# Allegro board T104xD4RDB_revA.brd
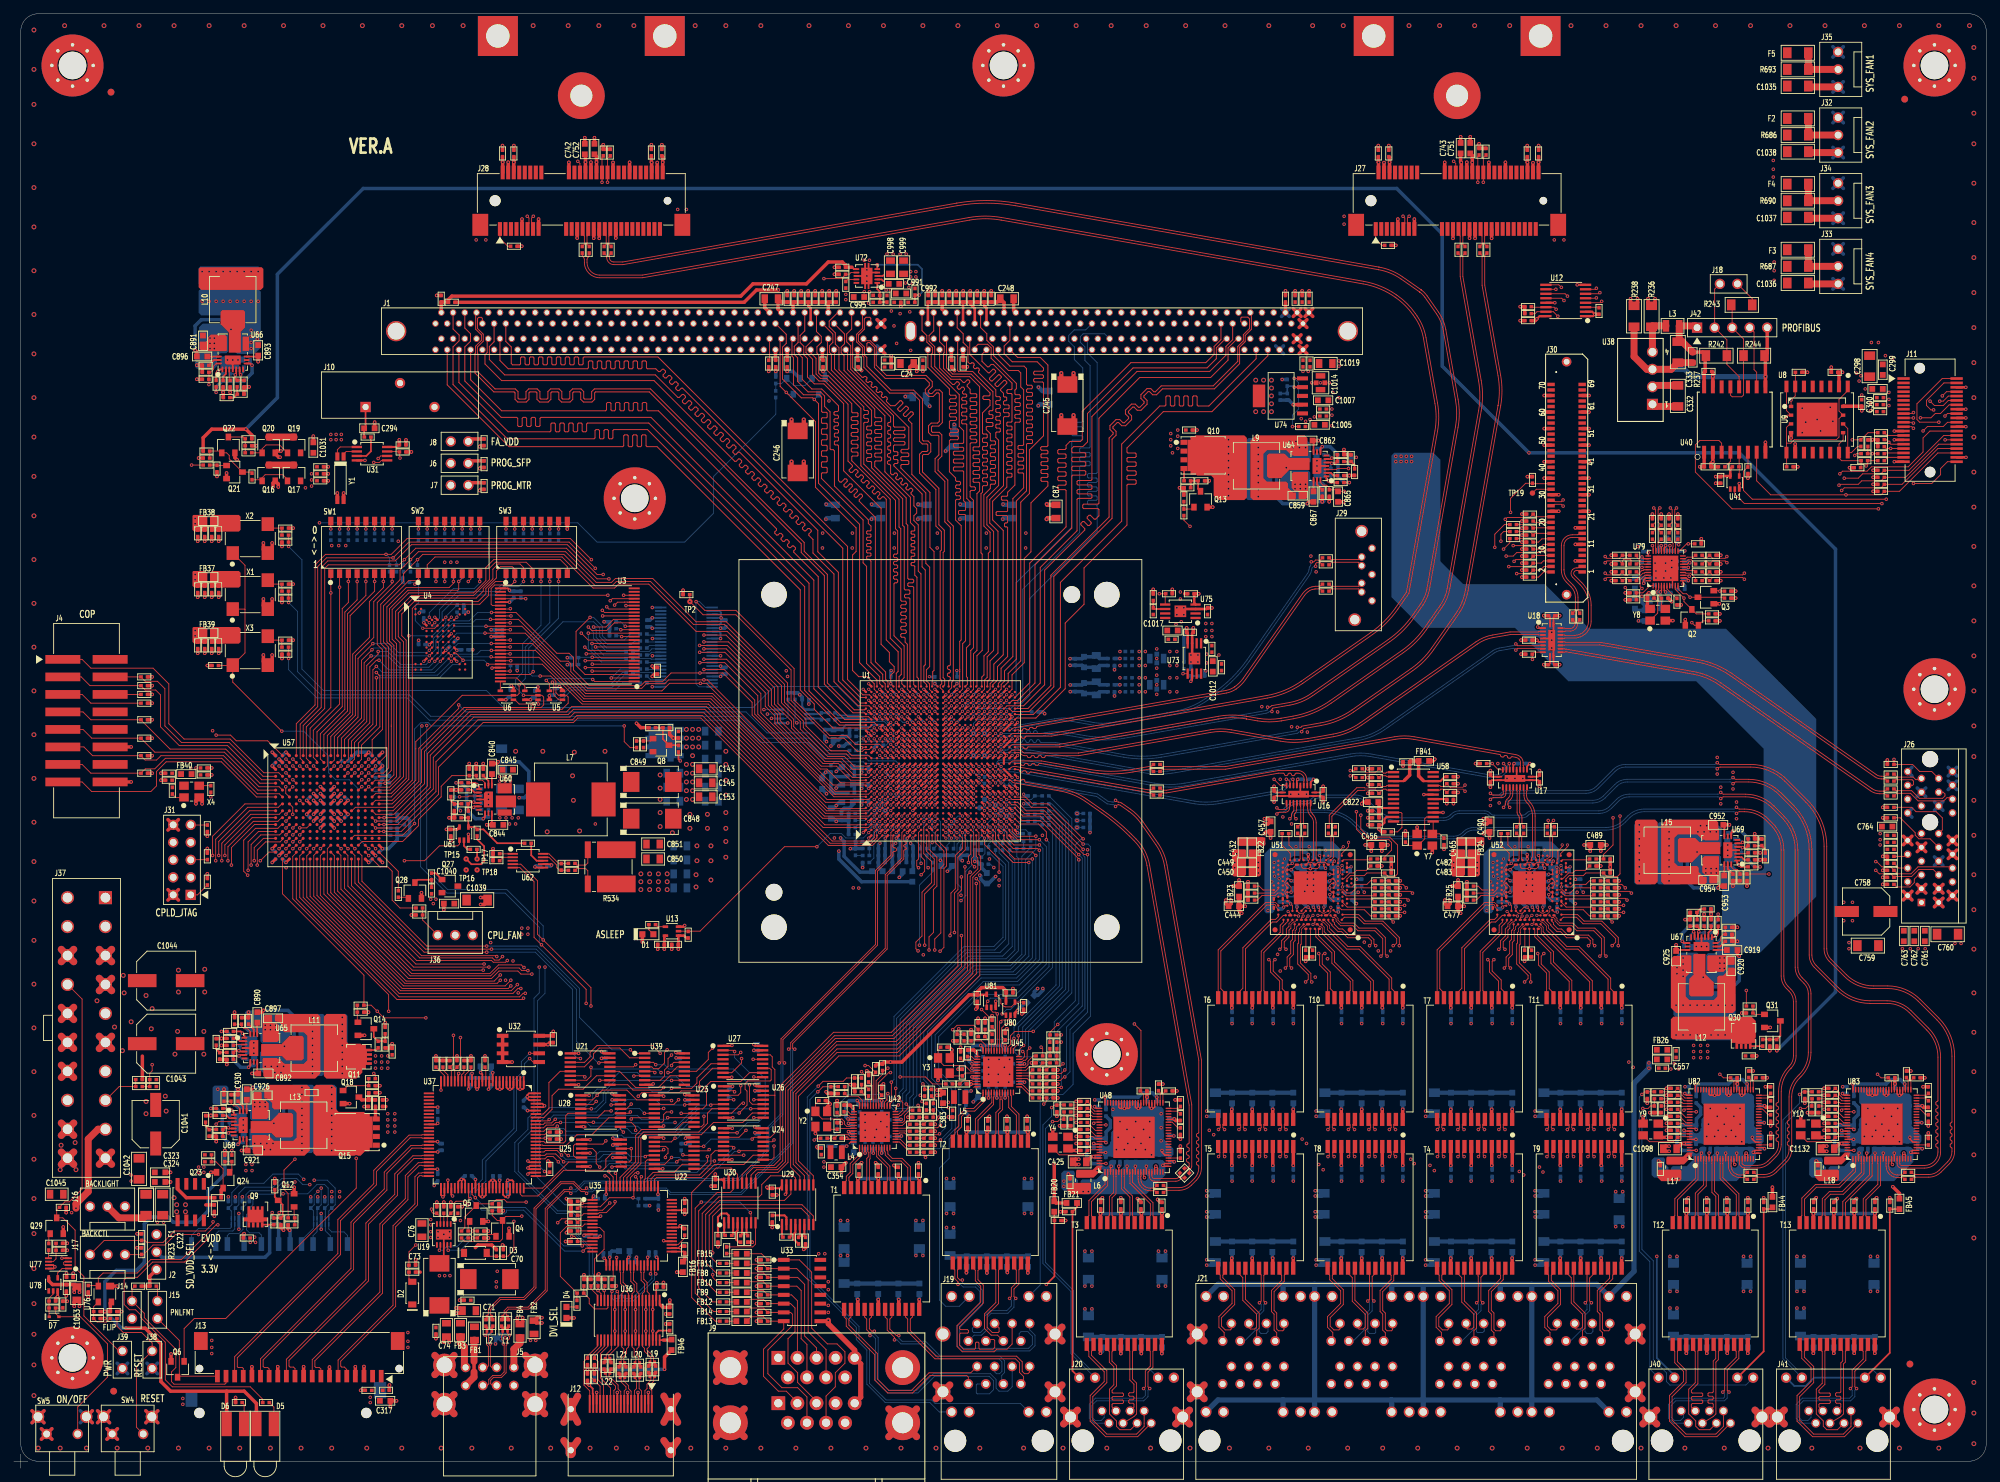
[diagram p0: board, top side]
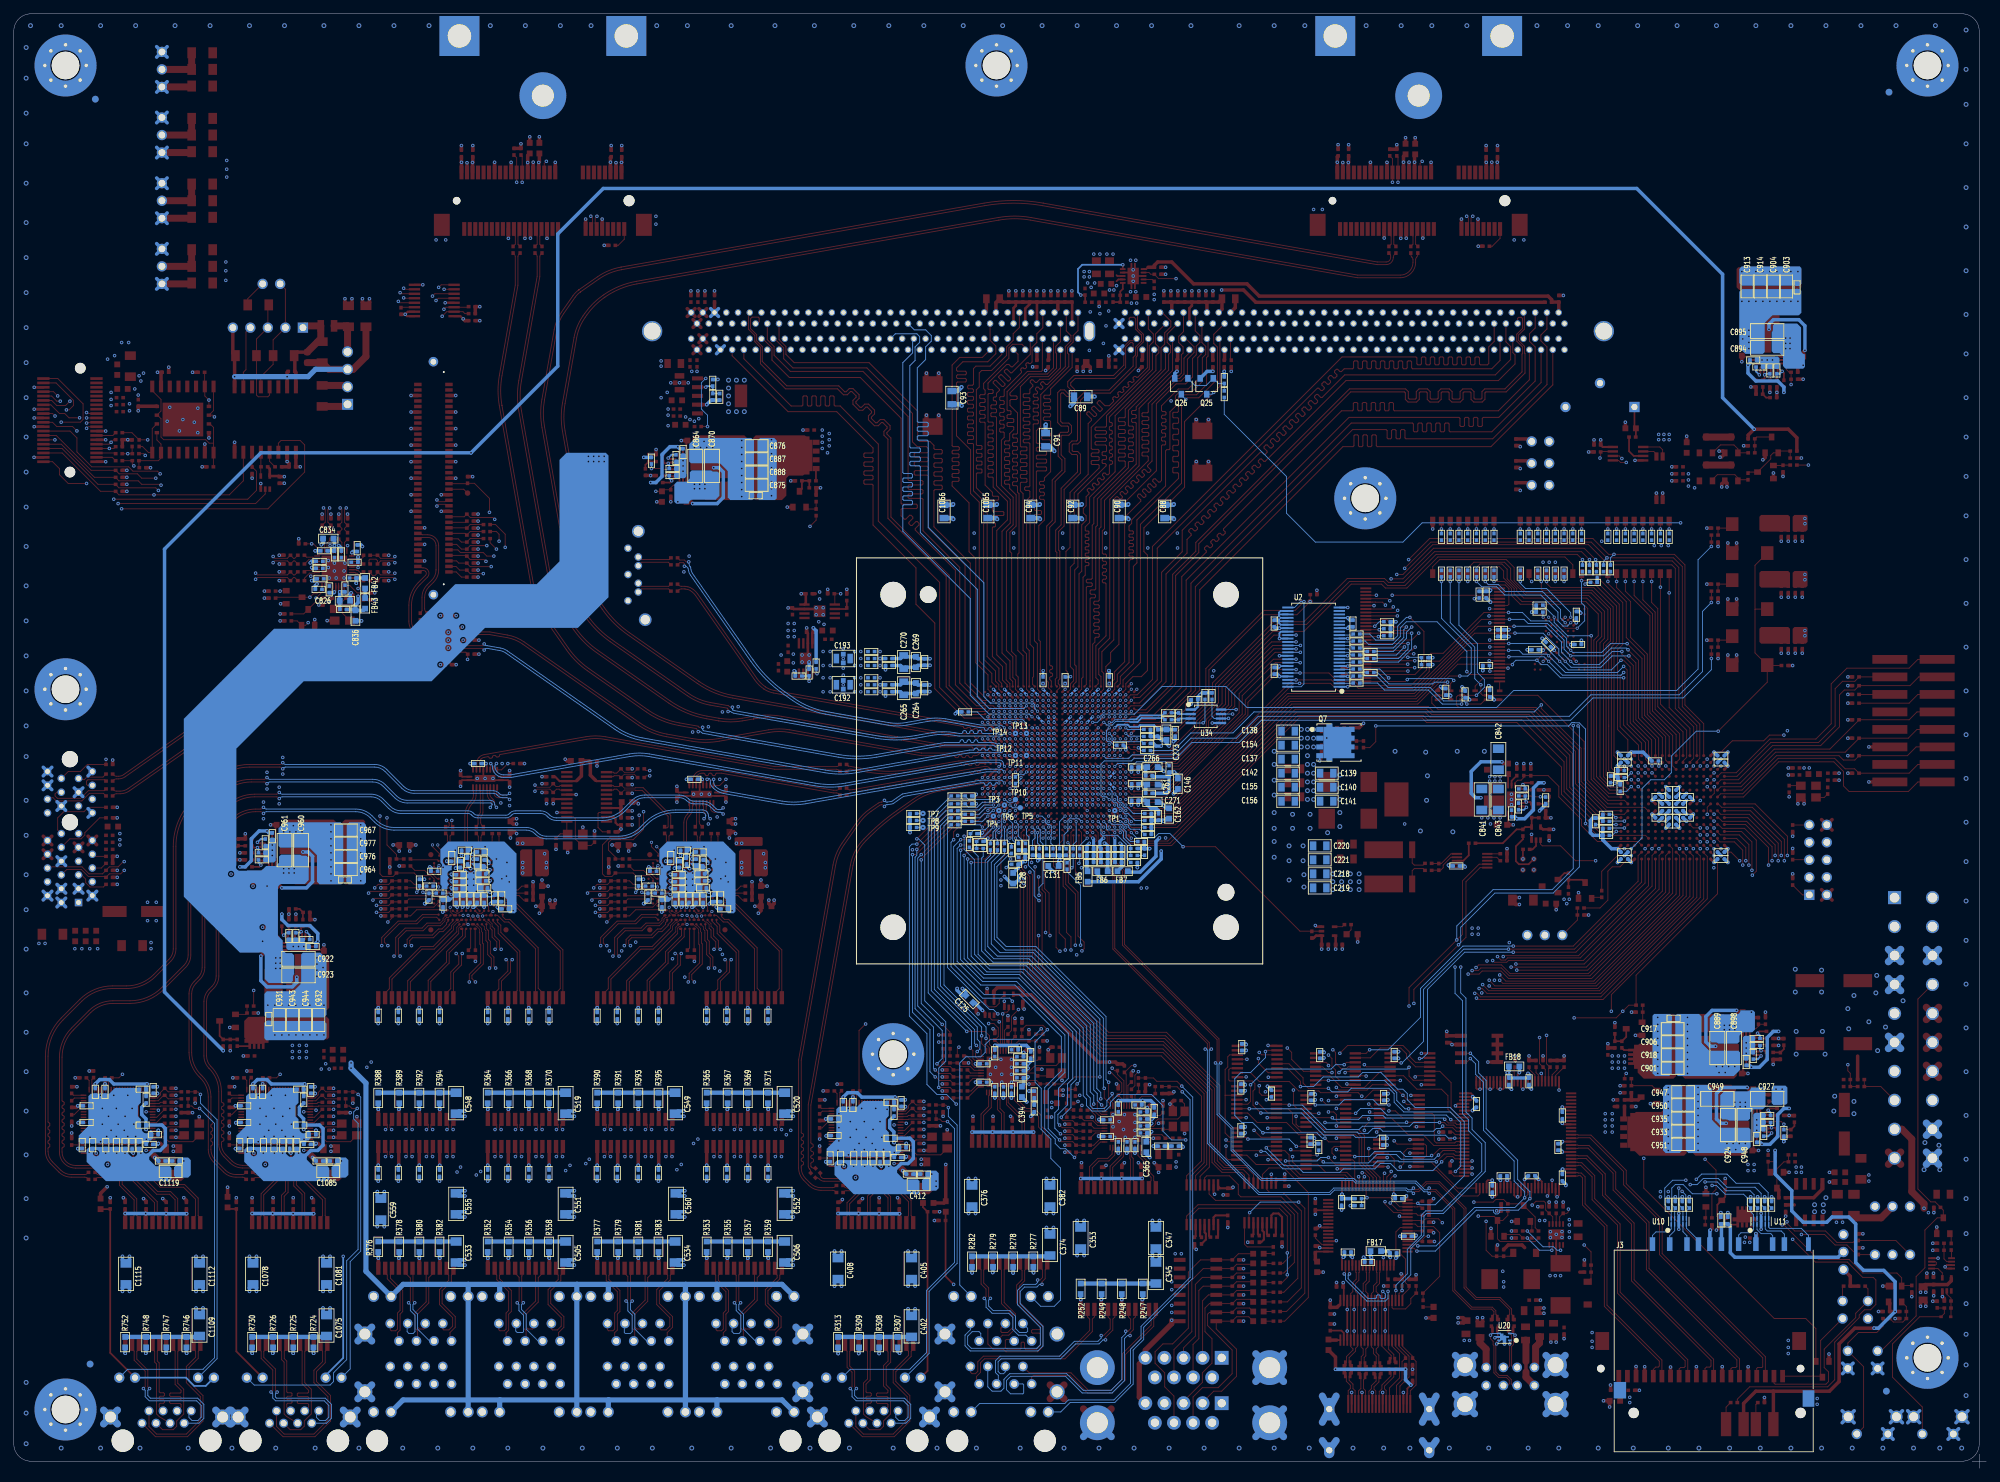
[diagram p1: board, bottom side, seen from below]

Outline 286.02 x 211.02 mm; copper layers: TOP, L2GND, L3SIG, L4PWR, L5PWR, L6SIG, L7GND, BOTTOM. Coordinates in mm from the lower left corner of the outline.
Outline path: 0,1.02 2.03,1.02 ; 1.02,2.03 1.02,0 ; 1.02,208.52 arc(1.75,210.28) 3.52,211.02 283.52,211.02 arc(285.28,210.28) 286.02,208.52 286.02,3.52 arc(285.28,1.75) 283.52,1.02 3.52,1.02 arc(1.75,1.75) 1.02,3.52 1.02,208.52

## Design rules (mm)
net group AURORA_EVTI_N: nets AURORA_EVTI_N N17558754
net group AURORA_EVTO_N: nets AURORA_EVTO_N N17558775
net group AURORA_HALT_N: nets AURORA_HALT_N N17558733
net group AURORA_REFCLK_N: nets AURORA_REFCLK_N N17952605
net group AURORA_REFCLK_P: nets AURORA_REFCLK_P N17952607
net group AURORA_RX_N: nets AURORA_RX_N N17557628
net group AURORA_RX_P: nets AURORA_RX_P N17557626
net group AURORA_TX: nets AURORA_TX_N AURORA_TX_P
net group CKE_ISO_EN: nets CKE_ISO_EN N20553507
net group CPLD_REFCLK: nets CPLD_REFCLK N17708927
net group DDR_REFCLK: nets DDR_REFCLK N17232338
net group EC1_INT_N: nets EC1_INT_N N17588858
net group EC1_LED0: nets EC1_LED0 N16870836
net group EC1_LED1: nets EC1_LED1 N16870842
net group EC1_MDI0: nets EC1_MDI0_N EC1_MDI0_P
net group EC1_MDI1: nets EC1_MDI1_N EC1_MDI1_P
net group EC1_MDI2: nets EC1_MDI2_N EC1_MDI2_P
net group EC1_MDI3: nets EC1_MDI3_N EC1_MDI3_P
net group EC1_MDX0: nets EC1_MDX0_N EC1_MDX0_P
net group EC1_MDX1: nets EC1_MDX1_N EC1_MDX1_P
net group EC1_MDX2: nets EC1_MDX2_N EC1_MDX2_P
net group EC1_MDX3: nets EC1_MDX3_N EC1_MDX3_P
net group EC1_PME_N: nets EC1_PME_N N17588905
net group EC1_REFCLK: nets EC1_REFCLK N17588897
net group EC2_INT_N: nets EC2_INT_N N17590707
net group EC2_LED0: nets EC2_LED0 N16974534
net group EC2_LED1: nets EC2_LED1 N16974536
net group EC2_MDI0: nets EC2_MDI0_N EC2_MDI0_P
net group EC2_MDI1: nets EC2_MDI1_N EC2_MDI1_P
net group EC2_MDI2: nets EC2_MDI2_N EC2_MDI2_P
net group EC2_MDI3: nets EC2_MDI3_N EC2_MDI3_P
net group EC2_MDX0: nets EC2_MDX0_N EC2_MDX0_P
net group EC2_MDX1: nets EC2_MDX1_N EC2_MDX1_P
net group EC2_MDX2: nets EC2_MDX2_N EC2_MDX2_P
net group EC2_MDX3: nets EC2_MDX3_N EC2_MDX3_P
net group EC2_PME_N: nets EC2_PME_N N17590774
net group EC2_REFCLK: nets EC2_REFCLK N17590767
net group EVDD_SEL: nets EVDD_SEL N20559490
net group FAN_PWM: nets FAN_PWM N17598342
net group FAN_TACH: nets FAN_TACH N17597092
net group GVDD_EN_N: nets GVDD_EN_N N19623885
net group IOPWR_EN: nets IOPWR_EN N18275588
net group LED_STATUS: nets LED_STATUS N22361656
net group MPEX1_REFCLK_N: nets MPEX1_REFCLK_N N17952565
net group MPEX1_REFCLK_P: nets MPEX1_REFCLK_P N17952563
net group MPEX1_RX_N: nets MPEX1_RX_N N16984265
net group MPEX1_RX_P: nets MPEX1_RX_P N16984263
net group MPEX1_TX_N: nets MPEX1_TX_N N16984233
net group MPEX1_TX_P: nets MPEX1_TX_P N16984231
net group MPEX2_REFCLK_N: nets MPEX2_REFCLK_N N17952569
net group MPEX2_REFCLK_P: nets MPEX2_REFCLK_P N17952567
net group MPEX2_RX_N: nets MPEX2_RX_N N16985388
net group MPEX2_RX_P: nets MPEX2_RX_P N16985386
net group MPEX2_TX_N: nets MPEX2_TX_N N16985356
net group MPEX2_TX_P: nets MPEX2_TX_P N16985354
net group N17055373: nets N17055373 N17055376
net group N17055394: nets N17055394 N17055396
net group N17055422: nets N17055422 N17055507
net group N17055459: nets N17055459 N17055529
net group N17055495: nets N17055419 N17055495
net group N17055527: nets N17055461 N17055527
net group N17056740: nets N17056740 N17056750
net group N17056764: nets N17056764 N17056766
net group N17056778: nets N17056778 N17056834
net group N17056796: nets N17056796 N17056846
net group N17056816: nets N17056776 N17056816
net group N17056844: nets N17056798 N17056844
net group N17246771: nets N17246719 N17246771
net group N17251677: nets N17251677 N17251680
net group N17251765: nets N17251765 N17251768
net group N17321019: nets N17321001 N17321019
net group N17399246: nets N17399246 N17399288
net group N17401544: nets N17400346 N17401544
net group N17424508: nets N17424508 N17424523
net group N17525004: nets N17525004 N17596169
net group N17639958: nets N17639958 N17639964
net group N17696038: nets N17696038 N17696060
net group N17742094: nets N17742094 N18275595
net group N18177051: nets N18177051 N18177080
net group N18275529: nets N18275529 N18275540
net group N18275559: nets N18275559 N18275570
net group N18569886: nets N17523697 N18569886
net group N19623883: nets N19623883 N19623968
net group N19675149: nets N19675149 N19675151
net group N20559492: nets N20559492 N20559589
net group N20559669: nets N20559669 N20559724
net group N23926306: nets N23926306 N23926329
net group PEX_REFCLK_N: nets N17952440 PEX_REFCLK_N
net group PEX_REFCLK_P: nets N17952438 PEX_REFCLK_P
net group PEX_RX_N: nets N17249127 PEX_RX_N
net group PEX_RX_P: nets N17249129 PEX_RX_P
net group PEX_TX_N: nets N17249250 PEX_TX_N
net group PEX_TX_P: nets N17249252 PEX_TX_P
net group PWR_GOOD: nets N18569887 PWR_GOOD
net group QSG1_INT_N: nets N17584869 QSG1_INT_N
net group QSG1_LED0: nets N17584990 QSG1_LED0
net group QSG1_LED1: nets N17584987 QSG1_LED1
net group QSG1_MDI0: nets QSG1_MDI0_N QSG1_MDI0_P
net group QSG1_MDI1: nets QSG1_MDI1_N QSG1_MDI1_P
net group QSG1_MDI2: nets QSG1_MDI2_N QSG1_MDI2_P
net group QSG1_MDI3: nets QSG1_MDI3_N QSG1_MDI3_P
net group QSG1_MDX0: nets QSG1_MDX0_N QSG1_MDX0_P
net group QSG1_MDX1: nets QSG1_MDX1_N QSG1_MDX1_P
net group QSG1_MDX2: nets QSG1_MDX2_N QSG1_MDX2_P
net group QSG1_MDX3: nets QSG1_MDX3_N QSG1_MDX3_P
net group QSG1_REFCLK_N: nets N17823659 QSG1_REFCLK_N
net group QSG1_REFCLK_P: nets N17823662 QSG1_REFCLK_P
net group QSG2_INT_N: nets N17640717 QSG2_INT_N
net group QSG2_LED0: nets N17585018 QSG2_LED0
net group QSG2_LED1: nets N17585015 QSG2_LED1
net group QSG2_MDI0: nets QSG2_MDI0_N QSG2_MDI0_P
net group QSG2_MDI1: nets QSG2_MDI1_N QSG2_MDI1_P
net group QSG2_MDI2: nets QSG2_MDI2_N QSG2_MDI2_P
net group QSG2_MDI3: nets QSG2_MDI3_N QSG2_MDI3_P
net group QSG2_MDX0: nets QSG2_MDX0_N QSG2_MDX0_P
net group QSG2_MDX1: nets QSG2_MDX1_N QSG2_MDX1_P
net group QSG2_MDX2: nets QSG2_MDX2_N QSG2_MDX2_P
net group QSG2_MDX3: nets QSG2_MDX3_N QSG2_MDX3_P
net group QSG2_REFCLK_N: nets N17824163 QSG2_REFCLK_N
net group QSG2_REFCLK_P: nets N17824166 QSG2_REFCLK_P
net group QSG3_LED0: nets N17585038 QSG3_LED0
net group QSG3_LED1: nets N17585035 QSG3_LED1
net group QSG3_MDI0: nets QSG3_MDI0_N QSG3_MDI0_P
net group QSG3_MDI1: nets QSG3_MDI1_N QSG3_MDI1_P
net group QSG3_MDI2: nets QSG3_MDI2_N QSG3_MDI2_P
net group QSG3_MDI3: nets QSG3_MDI3_N QSG3_MDI3_P
net group QSG3_MDX0: nets QSG3_MDX0_N QSG3_MDX0_P
net group QSG3_MDX1: nets QSG3_MDX1_N QSG3_MDX1_P
net group QSG3_MDX2: nets QSG3_MDX2_N QSG3_MDX2_P
net group QSG3_MDX3: nets QSG3_MDX3_N QSG3_MDX3_P
net group QSG4_LED0: nets N17585058 QSG4_LED0
net group QSG4_LED1: nets N17585055 QSG4_LED1
net group QSG4_MDI0: nets QSG4_MDI0_N QSG4_MDI0_P
net group QSG4_MDI1: nets QSG4_MDI1_N QSG4_MDI1_P
net group QSG4_MDI2: nets QSG4_MDI2_N QSG4_MDI2_P
net group QSG4_MDI3: nets QSG4_MDI3_N QSG4_MDI3_P
net group QSG4_MDX0: nets QSG4_MDX0_N QSG4_MDX0_P
net group QSG4_MDX1: nets QSG4_MDX1_N QSG4_MDX1_P
net group QSG4_MDX2: nets QSG4_MDX2_N QSG4_MDX2_P
net group QSG4_MDX3: nets QSG4_MDX3_N QSG4_MDX3_P
net group QSG5_LED0: nets N17585295 QSG5_LED0
net group QSG5_LED1: nets N17585292 QSG5_LED1
net group QSG5_MDI0: nets QSG5_MDI0_N QSG5_MDI0_P
net group QSG5_MDI1: nets QSG5_MDI1_N QSG5_MDI1_P
net group QSG5_MDI2: nets QSG5_MDI2_N QSG5_MDI2_P
net group QSG5_MDI3: nets QSG5_MDI3_N QSG5_MDI3_P
net group QSG5_MDX0: nets QSG5_MDX0_N QSG5_MDX0_P
net group QSG5_MDX1: nets QSG5_MDX1_N QSG5_MDX1_P
net group QSG5_MDX2: nets QSG5_MDX2_N QSG5_MDX2_P
net group QSG5_MDX3: nets QSG5_MDX3_N QSG5_MDX3_P
net group QSG6_LED0: nets N17585315 QSG6_LED0
net group QSG6_LED1: nets N17585312 QSG6_LED1
net group QSG6_MDI0: nets QSG6_MDI0_N QSG6_MDI0_P
net group QSG6_MDI1: nets QSG6_MDI1_N QSG6_MDI1_P
net group QSG6_MDI2: nets QSG6_MDI2_N QSG6_MDI2_P
net group QSG6_MDI3: nets QSG6_MDI3_N QSG6_MDI3_P
net group QSG6_MDX0: nets QSG6_MDX0_N QSG6_MDX0_P
net group QSG6_MDX1: nets QSG6_MDX1_N QSG6_MDX1_P
net group QSG6_MDX2: nets QSG6_MDX2_N QSG6_MDX2_P
net group QSG6_MDX3: nets QSG6_MDX3_N QSG6_MDX3_P
net group QSG7_LED0: nets N17585335 QSG7_LED0
net group QSG7_LED1: nets N17585332 QSG7_LED1
net group QSG7_MDI0: nets QSG7_MDI0_N QSG7_MDI0_P
net group QSG7_MDI1: nets QSG7_MDI1_N QSG7_MDI1_P
net group QSG7_MDI2: nets QSG7_MDI2_N QSG7_MDI2_P
net group QSG7_MDI3: nets QSG7_MDI3_N QSG7_MDI3_P
net group QSG7_MDX0: nets QSG7_MDX0_N QSG7_MDX0_P
net group QSG7_MDX1: nets QSG7_MDX1_N QSG7_MDX1_P
net group QSG7_MDX2: nets QSG7_MDX2_N QSG7_MDX2_P
net group QSG7_MDX3: nets QSG7_MDX3_N QSG7_MDX3_P
net group QSG8_LED0: nets N17585067 QSG8_LED0
net group QSG8_LED1: nets N17585063 QSG8_LED1
net group QSG8_MDI0: nets QSG8_MDI0_N QSG8_MDI0_P
net group QSG8_MDI1: nets QSG8_MDI1_N QSG8_MDI1_P
net group QSG8_MDI2: nets QSG8_MDI2_N QSG8_MDI2_P
net group QSG8_MDI3: nets QSG8_MDI3_N QSG8_MDI3_P
net group QSG8_MDX0: nets QSG8_MDX0_N QSG8_MDX0_P
net group QSG8_MDX1: nets QSG8_MDX1_N QSG8_MDX1_P
net group QSG8_MDX2: nets QSG8_MDX2_N QSG8_MDX2_P
net group QSG8_MDX3: nets QSG8_MDX3_N QSG8_MDX3_P
net group QSGMII1_RX: nets QSGMII1_RX_N QSGMII1_RX_P
net group QSGMII1_TX_N: nets N18629376 QSGMII1_TX_N
net group QSGMII1_TX_P: nets N18629379 QSGMII1_TX_P
net group QSGMII2_RX: nets QSGMII2_RX_N QSGMII2_RX_P
net group QSGMII2_TX_N: nets N18629428 QSGMII2_TX_N
net group QSGMII2_TX_P: nets N18629431 QSGMII2_TX_P
net group SATA_RX_N: nets N18629885 SATA_RX_N
net group SATA_RX_P: nets N18629888 SATA_RX_P
net group SATA_TX_N: nets N18629823 SATA_TX_N
net group SATA_TX_P: nets N18629826 SATA_TX_P
net group SD_REFCLK1_N: nets N17952585 SD_REFCLK1_N
net group SD_REFCLK1_P: nets N17952583 SD_REFCLK1_P
net group SD_REFCLK2_N: nets N17082300 SD_REFCLK2_N
net group SD_REFCLK2_P: nets N17082287 SD_REFCLK2_P
net group SD_RX2_N: nets N17082045 SD_RX2_N
net group SD_RX2_P: nets N17082047 SD_RX2_P
net group SD_RX3_N: nets N17082123 SD_RX3_N
net group SD_RX3_P: nets N17082121 SD_RX3_P
net group SD_RX4: nets SD_RX4_N SD_RX4_P
net group SD_TX2: nets SD_TX2_N SD_TX2_P
net group SD_TX3: nets SD_TX3_N SD_TX3_P
net group SD_TX4: nets SD_TX4_N SD_TX4_P
net group SENSEVDD: nets N17526574 SENSEVDD
net group SG1_INT_N: nets N18200354 SG1_INT_N
net group SG1_LED0: nets N18200232 SG1_LED0
net group SG1_LED1: nets N18200230 SG1_LED1
net group SG1_MDI0: nets SG1_MDI0_N SG1_MDI0_P
net group SG1_MDI1: nets SG1_MDI1_N SG1_MDI1_P
net group SG1_MDI2: nets SG1_MDI2_N SG1_MDI2_P
net group SG1_MDI3: nets SG1_MDI3_N SG1_MDI3_P
net group SG1_MDX0: nets SG1_MDX0_N SG1_MDX0_P
net group SG1_MDX1: nets SG1_MDX1_N SG1_MDX1_P
net group SG1_MDX2: nets SG1_MDX2_N SG1_MDX2_P
net group SG1_MDX3: nets SG1_MDX3_N SG1_MDX3_P
net group SG2_INT_N: nets N18205305 SG2_INT_N
net group SG2_LED0: nets N18205183 SG2_LED0
net group SG2_LED1: nets N18205181 SG2_LED1
net group SG2_MDI0: nets SG2_MDI0_N SG2_MDI0_P
net group SG2_MDI1: nets SG2_MDI1_N SG2_MDI1_P
net group SG2_MDI2: nets SG2_MDI2_N SG2_MDI2_P
net group SG2_MDI3: nets SG2_MDI3_N SG2_MDI3_P
net group SG2_MDX0: nets SG2_MDX0_N SG2_MDX0_P
net group SG2_MDX1: nets SG2_MDX1_N SG2_MDX1_P
net group SG2_MDX2: nets SG2_MDX2_N SG2_MDX2_P
net group SG2_MDX3: nets SG2_MDX3_N SG2_MDX3_P
net group SG_INT_N: nets N16894418 SG_INT_N
net group SG_LED0: nets N16892215 SG_LED0
net group SG_LED1: nets N16892219 SG_LED1
net group SG_MDI0: nets SG_MDI0_N SG_MDI0_P
net group SG_MDI1: nets SG_MDI1_N SG_MDI1_P
net group SG_MDI2: nets SG_MDI2_N SG_MDI2_P
net group SG_MDI3: nets SG_MDI3_N SG_MDI3_P
net group SG_MDX0: nets SG_MDX0_N SG_MDX0_P
net group SG_MDX1: nets SG_MDX1_N SG_MDX1_P
net group SG_MDX2: nets SG_MDX2_N SG_MDX2_P
net group SG_MDX3: nets SG_MDX3_N SG_MDX3_P
net group SGMII1_RX: nets SGMII1_RX_N SGMII1_RX_P
net group SGMII1_TX_N: nets N18200622 SGMII1_TX_N
net group SGMII1_TX_P: nets N18200620 SGMII1_TX_P
net group SGMII2_RX: nets SGMII2_RX_N SGMII2_RX_P
net group SGMII2_TX_N: nets N18205573 SGMII2_TX_N
net group SGMII2_TX_P: nets N18205571 SGMII2_TX_P
net group SGMII_RX_N: nets N17081957 SGMII_RX_N
net group SGMII_RX_P: nets N17081955 SGMII_RX_P
net group SGMII_TX_N: nets N16899338 SGMII_TX_N
net group SGMII_TX_P: nets N16899326 SGMII_TX_P
net group SYS_REFCLK: nets N17170143 SYS_REFCLK
net group SYS_REFCLK_N: nets N17952595 SYS_REFCLK_N
net group SYS_REFCLK_P: nets N17952601 SYS_REFCLK_P
net group USB1_DM: nets N17246518 USB1_DM
net group USB1_DP: nets N17246514 USB1_DP
net group USB1_FLG_N: nets N17246054 USB1_FLG_N
net group USB2_DM: nets N17246524 USB2_DM
net group USB2_DP: nets N17246522 USB2_DP
net group USB2_FLG_N: nets N17246089 USB2_FLG_N
net group USB_REFCLK: nets N17697384 USB_REFCLK
net group VDD_EN_N: nets N23926341 VDD_EN_N
net group 5V0_HDMI: nets 5V0_HDMI N17484070 N17484079
net group 5V0_USB1: nets USB1_VBUSCLMP
net group 5V0_USB2: nets USB2_VBUSCLMP
net group CK_N: nets DVI_TLC_N
net group CK_P: nets DVI_TLC_P
net group D0_N: nets DVI_TDC0_N
net group D0_P: nets DVI_TDC0_P
net group D1_N: nets DVI_TDC1_N
net group D1_P: nets DVI_TDC1_P
net group D2_N: nets DVI_TDC2_N
net group D2_P: nets DVI_TDC2_P
net group EC1_RXD1: nets N17588767
net group GND_PROFI: nets GND_PROFI ISO_RXD_TXD_N ISO_RXD_TXD_P N17551792 PROFI_PWR_OUT VCC_PROFI
net group INA_VCORE_N: nets INA_VCORE_N INA_VCORE_P N23927714
net group IOPWR_EN_N: nets IOPWR_EN_N N17696036 N18177053 N18275528 N18275558
net group MG_DDR_AC: nets DDR_MA0 DDR_MA1 DDR_MA2 DDR_MA3 DDR_MA4 DDR_MA5 DDR_MA6 DDR_MA7 DDR_MA8 DDR_MA9 DDR_MA10 DDR_MA11 DDR_MA12 DDR_MA13 DDR_MA14 DDR_MA15 DDR_MBA0 DDR_MBA1 DDR_MBA2 DDR_MCAS_N DDR_MCK0_N DDR_MCK0_P DDR_MCK1_N DDR_MCK1_P DDR_MCS0_N DDR_MCS1_N DDR_MCS2_N DDR_MCS3_N DDR_MODT0 DDR_MODT1 DDR_MRAS_N DDR_MWE_N
net group MG_DDR_DATA_BYTE0: nets DDR_DQ0 DDR_DQ1 DDR_DQ2 DDR_DQ3 DDR_DQ4 DDR_DQ5 DDR_DQ6 DDR_DQ7 DDR_MDM0 DDR_MDQS0_N DDR_MDQS0_P
net group MG_DDR_DATA_BYTE1: nets DDR_DQ8 DDR_DQ9 DDR_DQ10 DDR_DQ11 DDR_DQ12 DDR_DQ13 DDR_DQ14 DDR_DQ15 DDR_MDM1 DDR_MDQS1_N DDR_MDQS1_P
net group MG_DDR_DATA_BYTE2: nets DDR_DQ16 DDR_DQ17 DDR_DQ18 DDR_DQ19 DDR_DQ20 DDR_DQ21 DDR_DQ22 DDR_DQ23 DDR_MDM2 DDR_MDQS2_N DDR_MDQS2_P
net group MG_DDR_DATA_BYTE3: nets DDR_DQ24 DDR_DQ25 DDR_DQ26 DDR_DQ27 DDR_DQ28 DDR_DQ29 DDR_DQ30 DDR_DQ31 DDR_MDM3 DDR_MDQS3_N DDR_MDQS3_P
net group MG_DDR_DATA_BYTE4: nets DDR_DQ32 DDR_DQ33 DDR_DQ34 DDR_DQ35 DDR_DQ36 DDR_DQ37 DDR_DQ38 DDR_DQ39 DDR_MDM4 DDR_MDQS4_N DDR_MDQS4_P
net group MG_DDR_DATA_BYTE5: nets DDR_DQ40 DDR_DQ41 DDR_DQ42 DDR_DQ43 DDR_DQ44 DDR_DQ45 DDR_DQ46 DDR_DQ47 DDR_MDM5 DDR_MDQS5_N DDR_MDQS5_P
net group MG_DDR_DATA_BYTE6: nets DDR_DQ48 DDR_DQ49 DDR_DQ50 DDR_DQ51 DDR_DQ52 DDR_DQ53 DDR_DQ54 DDR_DQ55 DDR_MDM6 DDR_MDQS6_N DDR_MDQS6_P
net group MG_DDR_DATA_BYTE7: nets DDR_DQ56 DDR_DQ57 DDR_DQ58 DDR_DQ59 DDR_DQ60 DDR_DQ61 DDR_DQ62 DDR_DQ63 DDR_MDM7 DDR_MDQS7_N DDR_MDQS7_P
net group MG_DDR_DATA_BYTE_ECC: nets DDR_ECC0 DDR_ECC1 DDR_ECC2 DDR_ECC3 DDR_ECC4 DDR_ECC5 DDR_ECC6 DDR_ECC7 DDR_MDM8 DDR_MDQS8_N DDR_MDQS8_P
net group N16870296: nets N16870296 N17593781 N17593783 N17593791 N17593793
net group N16891950: nets N16891950 N16891952 N16891962 N16891966 N16891978
net group N16974225: nets N16974225 N16974227 N16974244 N16974248 N16974260
net group N17251653: nets N17251653 N17251663 N17251715 N17251719
net group N17251740: nets N17251740 N17251749 N17251753 N17251803
net group N17251827: nets N17251827 N17251836 N17251840 N17251892
net group N17252003: nets N17252003 N17252012 N17252016 N17252063
net group N17437909: nets N17437095 N17437909 N17497489
net group N17582904: nets N17582904 N17582906 N17582916 N17582920 N17582932
net group N17632317: nets N17632317 N17632319 N17632321 N17632325 N17632337
net group N17632726: nets N17632726 N17632728 N17632740 N17632744 N17632760
net group N17633242: nets N17633242 N17633244 N17633254 N17633258 N17633270
net group N17792541: nets N17792541 N17792549 N17792551 N17792553 N17792555
net group N17792543: nets N17792543 N17792589 N17792591 N17792593 N17792595
net group N17792545: nets N17792545 N17792630 N17792632 N17792634 N17792636
net group N17792547: nets N17792547 N17792669 N17792671 N17792673 N17792675
net group N18200115: nets N18200115 N18200130 N18200132 N18200134 N18200140
net group N18205066: nets N18205066 N18205081 N18205083 N18205085 N18205091
net group N18280039: nets N18280039 N18280059 N18280061 N18280157
net group SENSEVDDC: nets N17526575 N23929117 SENSEVDDC
net group SPI_CLK: nets N17200106 N17200136 N21754633 SPI_CLK
net group SPI_MISO: nets N17200115 N21754692 SPI_MISO
net group SPI_MOSI: nets N17200329 N21754708 SPI_MOSI
net group TEMP_DIODE_N: nets N17424740 N17424742 TEMP_DIODE_N TEMP_DIODE_P

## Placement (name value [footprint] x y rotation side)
C1  0.1uF  [0402]  116.21 169.67 270 top
C2  0.1uF  [0402]  135.64 169.67 270 top
C5  0.1uF  [0402]  137.67 169.67 270 top
C6  0.1uF  [0402]  136.65 169.67 270 top
C7  0.1uF  [0402]  141.73 169.67 270 top
C8  0.1uF  [0402]  133.6 169.67 270 top
C9  0.1uF  [0402]  113.16 169.67 270 top
C10  0.1uF  [0402]  114.17 169.67 270 top
C14  0.01uF  [0402]  119.25 169.67 270 top
C15  0.01uF  [0402]  117.22 169.67 270 top
C17  1000pF  [0402]  112.14 169.67 270 top
C18  1000pF  [0402]  139.7 169.67 270 top
C21  0.1uF  [0402]  63.5 169.16 180 top
C22  0.1uF  [0402]  61.98 169.67 90 top
C23  0.1uF  [0402]  184.4 169.67 90 top
C24  47uF  [0805]  129.54 160.27 0 top
C25  0.1uF  [0402]  126.75 159.77 0 top
C26  0.1uF  [0402]  128.14 169.16 0 top
C27  0.1uF  [0402]  131.83 160.27 270 top
C28  0.1uF  [0402]  126.75 160.78 0 top
C29  0.1uF  [0402]  93.35 115.7 270 top
C30  0.1uF  [0402]  103.25 122.56 90 bottom
C31  0.1uF  [0402]  103.25 115.7 270 bottom
C32  0.1uF  [0402]  91.82 122.56 90 bottom
C33  1uF  [0402]  59.18 119.51 180 bottom
C34  0.1uF  [0402]  65.41 118.75 0 bottom
C35  0.1uF  [0402]  63.5 119.51 45 bottom
C36  0.1uF  [0402]  59.44 123.83 90 bottom
C38  0.1uF  [0402]  72.52 126.75 270 bottom
C39  0.1uF  [0402]  75.57 112.27 90 bottom
C40  0.1uF  [0402]  78.36 112.65 90 bottom
C41  1uF  [0402]  69.85 121.16 90 bottom
C42  0.1uF  [0402]  70.87 121.16 90 bottom
C43  0.1uF  [0402]  72.01 112.39 90 bottom
C44  1uF  [0402]  267.97 154.56 90 top
C45  0.1uF  [0402]  264.03 159 180 top
C46  1uF  [0402]  38.48 35.94 90 bottom
C47  0.1uF  [0402]  37.47 35.94 90 bottom
C48  0.1uF  [0402]  219.58 166.5 180 top
C49  0.1uF  [0402]  95.89 76.01 180 top
C50  0.1uF  [0402]  93.85 76.01 180 top
C51  10pF  [0402]  145.92 90.93 0 bottom
C52  10pF  [0402]  147.57 96.39 180 bottom
C55  0.1uF  [0402]  165.74 98.68 180 top
C56  0.1uF  [0402]  170.12 42.48 45 top
C57  0.1uF  [0402]  169.42 43.18 45 top
C58  0.1uF  [0402]  165.74 97.66 180 top
C59  0.1uF  [0402]  165.74 101.09 180 top
C60  0.1uF  [0402]  165.74 102.11 180 top
C61  0.01uF  [0402]  187.33 99.95 0 bottom
C62  0.01uF  [0402]  182.75 97.79 270 top
C63  0.01uF  [0402]  189.87 97.79 270 top
C64  0.01uF  [0402]  218.69 102.23 0 bottom
C65  0.01uF  [0402]  221.23 100.08 270 top
C66  0.01uF  [0402]  214.12 100.08 270 top
C67  0.01uF  [0402]  223.01 116.59 0 top
C68  0.01uF  [0402]  219.71 120.14 180 top
C69  0.01uF  [0402]  223.01 123.7 0 top
C70  100uF  [7343]  68.96 27.43 0 top
C71  10uF  [0805]  66.04 22.86 180 top
C72  1000pF  [0402]  65.79 24.38 180 top
C73  100uF  [7343]  61.72 26.67 90 top
C74  10uF  [0805]  62.74 20.07 270 top
C75  1000pF  [0402]  61.21 19.94 270 top
C76  10uF  [0805]  59.18 34.54 270 top
C77  0.1uF  [0402]  64.39 37.47 90 top
C78  0.1uF  [0402]  123.57 88.9 180 bottom
C79  0.1uF  [0402]  108.08 55.24 270 bottom
C80  0.1uF  [0402]  107.95 61.09 270 bottom
C81  0.1uF  [0402]  96.65 59.94 270 bottom
C82  0.1uF  [0402]  85.85 59.94 270 bottom
C83  0.1uF  [0402]  87.5 47.37 270 bottom
C84  0.1uF  [0402]  87.38 53.85 270 bottom
C85  0.1uF  [0402]  108.08 49.02 270 bottom
C86  0.1uF  [0402]  98.04 47.5 270 bottom
C87  22uF  [0805]  151.13 138.81 90 top
C88  22uF  [0805]  119.13 138.81 90 bottom
C89  22uF  [0805]  131.32 155.45 180 bottom
C90  22uF  [0805]  125.73 138.81 90 bottom
C91  22uF  [0805]  136.4 149.22 270 bottom
C92  22uF  [0805]  132.46 138.81 90 bottom
C93  22uF  [0805]  149.99 155.32 90 bottom
C94  22uF  [0805]  138.56 138.81 90 bottom
C95  0.1uF  [0201]  130.76 97.81 0 bottom
C96  0.1uF  [0201]  130.76 98.61 0 bottom
C97  2.2uF  [0402]  129.92 88.9 180 bottom
C98  2.2uF  [0402]  129.92 87.88 180 bottom
C99  0.1uF  [0201]  132.36 112.62 315 bottom
C100  0.1uF  [0201]  125.96 112.62 315 bottom
C101  0.1uF  [0201]  133.17 108.62 135 bottom
C102  0.1uF  [0201]  129.16 112.62 315 bottom
C103  0.1uF  [0201]  143.57 112.62 225 bottom
C104  0.1uF  [0201]  129.96 108.62 135 bottom
C105  0.1uF  [0201]  129.56 96.61 270 bottom
C106  0.1uF  [0201]  130.36 96.61 270 bottom
C107  3000pF  [0402]  127.89 89.92 0 bottom
C108  2.2uF  [0402]  127.89 87.88 0 bottom
C109  0.1uF  [0201]  141.97 112.62 225 bottom
C110  0.1uF  [0201]  139.57 112.62 225 bottom
C111  0.1uF  [0201]  130.76 112.62 315 bottom
C112  0.1uF  [0201]  127.56 112.62 315 bottom
C113  0.1uF  [0201]  137.17 108.62 45 bottom
C114  0.1uF  [0201]  135.17 108.62 90 bottom
C115  0.1uF  [0201]  136.37 112.62 225 bottom
C116  0.1uF  [0201]  135.97 108.62 90 bottom
C117  0.1uF  [0201]  131.56 108.62 135 bottom
C118  2.2uF  [0402]  127.89 88.9 0 bottom
C119  0.1uF  [0201]  137.97 112.62 225 bottom
C120  0.1uF  [0201]  129.16 98.61 180 bottom
C121  0.1uF  [0201]  129.16 97.81 180 bottom
C122  3000pF  [0402]  125.86 89.92 0 bottom
C123  2.2uF  [0402]  125.86 88.9 0 bottom
C124  2.2uF  [0402]  125.86 87.88 0 bottom
C125  10uF  [0603]  147.45 68.07 225 bottom
C126  0.1uF  [0201]  137.57 96.61 270 bottom
C127  0.1uF  [0201]  138.37 96.61 270 bottom
C128  10uF  [0603]  141.1 85.6 270 bottom
C129  0.1uF  [0201]  136.77 96.61 270 bottom
C130  0.1uF  [0201]  135.97 96.61 270 bottom
C131  10uF  [0603]  135.26 87.38 0 bottom
C132  0.1uF  [0201]  135.17 96.61 270 bottom
C133  0.1uF  [0201]  133.57 96.61 270 bottom
C134  0.1uF  [0201]  132.76 96.61 270 bottom
C135  0.1uF  [0201]  131.96 96.61 270 bottom
C136  0.1uF  [0201]  131.16 96.61 270 bottom
C137  22uF  [0805]  101.22 102.87 0 bottom
C138  22uF  [0805]  101.22 106.93 0 bottom
C139  22uF  [0805]  95.63 100.84 180 bottom
C140  22uF  [0805]  95.63 98.81 180 bottom
C141  22uF  [0805]  95.63 96.77 180 bottom
C142  22uF  [0805]  101.22 100.84 0 bottom
C143  22uF  [0805]  100.33 101.47 0 top
C144  0.1uF  [0201]  126.76 100.61 135 bottom
C145  22uF  [0805]  100.33 99.44 0 top
C146  10uF  [0603]  117.22 99.31 270 bottom
C147  0.1uF  [0201]  129.16 106.62 180 bottom
C148  0.1uF  [0201]  129.16 105.82 180 bottom
C149  0.1uF  [0201]  129.16 105.02 180 bottom
C150  0.1uF  [0201]  129.16 104.22 180 bottom
C151  0.1uF  [0201]  129.16 103.42 180 bottom
C152  0.1uF  [0201]  129.16 101.82 180 bottom
C153  22uF  [0805]  100.33 97.41 0 top
C154  22uF  [0805]  101.22 104.9 0 bottom
C155  22uF  [0805]  101.22 98.81 0 bottom
C156  22uF  [0805]  101.22 96.77 0 bottom
C161  0.1uF  [0201]  126.76 99.01 225 bottom
C162  10uF  [0603]  118.49 95 90 bottom
C163  0.1uF  [0201]  129.16 100.21 180 bottom
C164  0.1uF  [0201]  129.16 99.41 180 bottom
C165  0.1uF  [0201]  135.57 100.21 0 bottom
C166  0.1uF  [0201]  130.76 103.42 0 bottom
C167  0.1uF  [0201]  137.17 101.01 180 bottom
C168  0.1uF  [0201]  137.17 105.02 180 bottom
C169  0.1uF  [0201]  132.36 101.82 180 bottom
C170  0.1uF  [0201]  129.16 101.01 180 bottom
C171  0.1uF  [0201]  137.17 105.82 0 bottom
C172  0.1uF  [0201]  135.57 101.82 0 bottom
C173  0.1uF  [0201]  130.76 100.21 180 bottom
C174  0.1uF  [0201]  127.96 104.62 270 bottom
C175  0.1uF  [0201]  137.17 104.22 0 bottom
C176  0.1uF  [0201]  135.57 103.42 180 bottom
C177  0.1uF  [0201]  130.76 107.42 180 bottom
C178  0.1uF  [0201]  137.17 103.42 180 bottom
C179  0.1uF  [0201]  138.77 101.82 0 bottom
C180  0.1uF  [0201]  130.76 105.82 180 bottom
C181  0.1uF  [0201]  130.76 106.62 0 bottom
C182  0.1uF  [0201]  130.76 104.22 180 bottom
C183  0.1uF  [0201]  127.56 97.81 180 bottom
C184  0.1uF  [0201]  135.57 106.62 180 bottom
C185  0.1uF  [0201]  137.17 97.81 180 bottom
C186  0.1uF  [0201]  132.36 105.02 0 bottom
C187  0.1uF  [0201]  135.57 101.01 180 bottom
C188  0.1uF  [0201]  135.57 105.82 0 bottom
C189  0.1uF  [0201]  135.57 104.22 0 bottom
C190  0.1uF  [0201]  132.36 101.01 0 bottom
C191  0.1uF  [0201]  132.36 97.81 0 bottom
C192  NFM21PC225B0J3  [NFM21]  165.74 113.66 0 bottom
C193  NFM21PC225B0J3  [NFM21]  165.74 117.47 180 bottom
C194  0.1uF  [0201]  132.36 107.42 180 bottom
C195  0.1uF  [0201]  132.36 105.82 180 bottom
C196  0.1uF  [0201]  135.57 107.42 0 bottom
C197  0.1uF  [0201]  132.36 104.22 180 bottom
C198  1500pF  [0201]  137.17 106.62 180 bottom
C199  1500pF  [0201]  132.36 103.42 0 bottom
C200  1500pF  [0201]  130.76 105.02 0 bottom
C201  1500pF  [0201]  132.36 106.62 0 bottom
C202  1500pF  [0201]  135.57 105.02 180 bottom
C203  1500pF  [0201]  135.57 97.81 180 bottom
C204  1500pF  [0201]  137.17 101.82 0 bottom
C205  1500pF  [0201]  130.76 101.82 180 bottom
C206  1500pF  [0201]  132.36 100.21 180 bottom
C207  1500pF  [0201]  137.17 99.41 180 bottom
C208  1500pF  [0201]  138.77 99.41 180 bottom
C210  2.2uF  [0402]  161.67 113.66 180 bottom
C211  2.2uF  [0402]  161.67 112.65 180 bottom
C212  3000pF  [0402]  161.67 114.68 180 bottom
C213  0.1uF  [0201]  137.97 107.42 180 bottom
C214  0.1uF  [0201]  138.77 105.82 0 bottom
C215  0.1uF  [0201]  138.77 105.02 0 bottom
C216  0.1uF  [0201]  138.77 104.22 0 bottom
C217  0.1uF  [0201]  138.77 101.01 180 bottom
C218  22uF  [0805]  96.65 86.23 0 bottom
C219  22uF  [0805]  96.65 84.2 0 bottom
C220  22uF  [0805]  96.65 90.3 0 bottom
C221  22uF  [0805]  96.65 88.27 0 bottom
C226  0.1uF  [0201]  137.17 98.61 0 bottom
C227  0.1uF  [0201]  130.76 99.41 0 bottom
C228  0.1uF  [0201]  132.36 99.41 0 bottom
C229  0.1uF  [0201]  137.17 100.21 0 bottom
C230  0.1uF  [0201]  135.57 98.61 0 bottom
C231  0.1uF  [0201]  133.17 98.61 0 bottom
C232  0.1uF  [0201]  138.37 98.21 270 bottom
C233  1500pF  [0201]  135.57 99.41 180 bottom
C234  1500pF  [0201]  130.76 101.01 0 bottom
C237  2.2uF  [0402]  161.67 116.46 180 bottom
C238  2.2uF  [0402]  161.67 118.49 180 bottom
C239  3000pF  [0402]  161.67 117.47 180 bottom
C240  0.1uF  [0201]  141.97 108.22 0 bottom
C241  0.1uF  [0201]  141.97 105.82 0 bottom
C242  0.1uF  [0201]  141.97 103.42 0 bottom
C243  0.1uF  [0201]  141.97 100.21 0 bottom
C244  0.1uF  [0201]  141.97 97.81 0 bottom
C245  470uF  [7343]  152.78 154.18 270 top
C246  470uF  [7343]  113.67 147.45 270 top
C247  47uF  [0805]  109.86 169.67 180 top
C248  47uF  [0805]  144.02 169.67 0 top
C249  0.1uF  [0402]  134.62 169.67 90 top
C250  0.1uF  [0402]  112.14 160.27 270 top
C251  0.1uF  [0402]  117.35 160.27 270 top
C252  0.1uF  [0402]  118.24 169.67 90 top
C253  0.1uF  [0402]  132.59 169.67 90 top
C254  0.1uF  [0402]  140.72 169.67 90 top
C255  0.1uF  [0402]  136.02 160.27 270 top
C256  0.1uF  [0402]  138.68 169.67 90 top
C257  0.1uF  [0402]  137.67 160.27 270 top
C258  0.1uF  [0402]  115.19 169.67 90 top
C259  0.1uF  [0402]  110.49 160.27 270 top
C260  0.1uF  [0402]  122.43 160.27 270 top
C261  10uF  [0603]  120.9 99.19 180 bottom
C262  1uF  [0402]  123.44 99.31 0 bottom
C263  3000pF  [0402]  153.92 113.16 90 bottom
C264  4.7uF  [0603]  155.19 113.16 90 bottom
C265  47uF  [0805]  156.97 113.16 90 bottom
C266  10uF  [0603]  120.9 101.73 180 bottom
C267  1uF  [0402]  123.44 101.73 0 bottom
C268  3000pF  [0402]  153.92 116.97 90 bottom
C269  4.7uF  [0603]  155.19 116.97 90 bottom
C270  47uF  [0805]  156.97 116.97 90 bottom
C271  10uF  [0603]  120.9 96.65 180 bottom
C272  1uF  [0402]  123.44 96.9 0 bottom
C273  10uF  [0603]  118.87 106.43 270 bottom
C274  1uF  [0402]  120.14 106.68 270 bottom
C275  0.1uF  [0402]  112.01 33.53 180 top
C276  0.1uF  [0402]  109.98 40.13 270 top
C277  0.1uF  [0402]  109.98 36.19 270 top
C278  0.1uF  [0402]  113.79 33.02 270 top
C279  0.1uF  [0402]  114.81 33.02 270 top
C280  100pF  [0402]  108.84 28.96 180 top
C281  100pF  [0402]  108.84 26.42 180 top
C282  100pF  [0402]  108.84 25.15 180 top
C283  100pF  [0402]  108.84 27.69 180 top
C284  0.1uF  [0402]  103.63 33.78 180 top
C285  0.1uF  [0402]  101.73 41.4 270 top
C286  0.1uF  [0402]  105.41 33.27 270 top
C287  0.1uF  [0402]  102.11 33.27 270 top
C288  0.1uF  [0402]  106.43 33.27 270 top
C289  100pF  [0402]  108.84 30.23 180 top
C290  100pF  [0402]  108.84 22.61 180 top
C291  100pF  [0402]  108.84 21.34 180 top
C292  100pF  [0402]  108.84 23.88 180 top
C293  0.1uF  [0402]  78.23 62.23 270 top
C294  10uF  [0603]  51.56 150.88 0 top
C295  0.1uF  [0402]  56.39 148.46 0 top
C296  1000pF  [0402]  117.09 109.09 90 bottom
C297  0.1uF  [0402]  114.81 111.51 0 bottom
C298  10uF  [1206]  269.11 159.89 90 top
C299  0.1uF  [0603]  271.02 159.38 90 top
C300  10uF  [0603]  270.26 156.59 180 top
C301  0.1uF  [0402]  270.64 155.32 180 top
C302  0.1uF  [0402]  270.64 154.31 180 top
C303  0.1uF  [0402]  270.64 153.29 180 top
C304  0.1uF  [0402]  95.12 20.45 90 top
C305  0.1uF  [0402]  83.19 13.21 90 top
C306  0.1uF  [0402]  81.28 37.72 0 top
C307  0.1uF  [0402]  93.73 26.29 0 top
C308  0.1uF  [0402]  95.12 22.86 270 top
C309  0.1uF  [0402]  85.22 39.12 0 bottom
C310  0.1uF  [0402]  92.58 31.37 0 bottom
C311  0.1uF  [0402]  89.66 29.84 0 bottom
C312  0.1uF  [0402]  97.28 37.97 90 top
C313  0.1uF  [0402]  93.47 38.61 270 bottom
C314  0.1uF  [0402]  83.82 33.66 180 bottom
C315  0.1uF  [0402]  97.28 31.75 90 top
C316  0.1uF  [0402]  85.98 31.24 180 bottom
C317  10uF  [0603]  53.85 9.78 0 top
C318  0.1uF  [0402]  53.98 11.3 0 top
C319  0.1uF  [0402]  51.44 11.3 180 top
C320  0.1uF  [0402]  66.29 56.13 270 bottom
C321  0.1uF  [0402]  69.22 56.13 270 bottom
C322  10uF  [1206]  21.59 38.23 270 top
C323  0.1uF  [0603]  21.21 42.93 0 top
C324  0.1uF  [0603]  21.21 41.53 0 top
C325  0.1uF  [0402]  62.1 46.61 270 bottom
C326  0.1uF  [0402]  61.47 42.16 270 bottom
C327  0.1uF  [0402]  61.47 51.18 270 bottom
C328  0.1uF  [0402]  69.98 42.42 180 bottom
C329  0.1uF  [0402]  73.91 52.83 90 bottom
C330  0.1uF  [0402]  65.91 42.42 180 bottom
C331  0.1uF  [0402]  71.63 40.51 270 bottom
C332  10uF  [1206]  241.3 155.57 270 top
C333  10uF  [1206]  241.3 161.93 270 top
C334  0.1uF  [0402]  245.75 159.13 0 top
C336  0.1uF  [0402]  97.92 53.85 270 bottom
C337  0.1uF  [0402]  247.52 143.38 270 top
C338  0.1uF  [0402]  245.62 145.29 0 top
C339  0.01uF  [0402]  125.35 43.18 270 top
C341  0.01uF  [0402]  122.56 43.18 270 top
C342  0.01uF  [0402]  131.19 43.18 270 top
C343  10pF  [0402]  130.81 50.93 0 top
C344  0.01uF  [0402]  128.27 43.18 270 top
C345  1000pF  [1206]  120.4 28.32 90 bottom
C346  10pF  [0402]  119.51 47.88 0 top
C347  1000pF  [1206]  120.4 33.4 270 bottom
C348  470pF  [0402]  118.49 54.86 270 top
C349  470pF  [0402]  121.92 56.13 270 top
C350  4.7pF  [0402]  117.22 53.34 0 top
C351  4.7pF  [0402]  119.38 49.66 90 top
C352  1000pF  [0402]  117.6 46.74 180 bottom
C353  1000pF  [1206]  131.32 33.4 270 bottom
C354  4.7uF  [0603]  119.25 43.69 0 top
C355  0.1uF  [0402]  117.09 45.97 90 top
C356  0.1uF  [0402]  127.51 50.55 180 bottom
C357  0.1uF  [0402]  127.51 48.13 180 bottom
C358  0.1uF  [0402]  122.94 52.7 0 bottom
C359  0.1uF  [0402]  125.86 52.2 270 bottom
C360  0.1uF  [0402]  122.17 48.64 0 bottom
C361  0.1uF  [0402]  122.17 49.66 0 bottom
C362  0.1uF  [0402]  122.17 50.67 0 bottom
C363  0.1uF  [0402]  123.44 46.86 90 bottom
C364  0.1uF  [0402]  125.86 46.86 90 bottom
C365  4.7uF  [0603]  121.79 46.61 270 bottom
C366  0.1uF  [0402]  122.17 51.69 0 bottom
C367  0.1uF  [0402]  124.59 46.86 90 bottom
C368  0.01uF  [0402]  141.22 49.91 270 top
C369  0.1uF  [0402]  151.38 35.94 0 top
C370  0.01uF  [0402]  146.94 49.91 270 top
C371  0.01uF  [0402]  138.3 49.91 270 top
C372  10pF  [0402]  148.72 58.8 0 top
C373  0.01uF  [0402]  144.02 49.91 270 top
C374  1000pF  [1206]  135.76 32.39 90 bottom
C375  10pF  [0402]  137.67 55.75 0 top
C376  1000pF  [1206]  147.07 39.5 270 bottom
C377  470pF  [0402]  136.78 62.48 270 top
C378  470pF  [0402]  139.83 64.13 90 top
C379  4.7pF  [0402]  134.87 61.09 0 top
C380  4.7pF  [0402]  137.54 57.4 90 top
C381  1000pF  [0402]  138.05 52.2 270 bottom
C382  1000pF  [1206]  135.76 39.5 270 bottom
C383  4.7uF  [0603]  134.75 53.72 90 top
C384  0.1uF  [0402]  136.14 51.44 270 top
C385  0.1uF  [0402]  145.42 56.01 180 bottom
C386  0.1uF  [0402]  145.42 58.67 180 bottom
C387  0.1uF  [0402]  143.76 60.2 270 bottom
C388  0.1uF  [0402]  140.84 60.71 0 bottom
C389  0.1uF  [0402]  140.08 59.69 0 bottom
C390  0.1uF  [0402]  140.08 56.64 0 bottom
C391  0.1uF  [0402]  140.08 58.67 0 bottom
C392  0.1uF  [0402]  143.76 54.86 90 bottom
C393  0.1uF  [0402]  141.35 54.86 90 bottom
C394  4.7uF  [0603]  139.83 54.61 270 bottom
C395  0.1uF  [0402]  140.08 57.66 0 bottom
C396  0.1uF  [0402]  142.49 54.86 90 bottom
C397  0.01uF  [0402]  163.45 38.1 270 top
C398  0.1uF  [0402]  153.04 37.21 180 top
C399  0.01uF  [0402]  166.5 38.1 270 top
C400  0.01uF  [0402]  157.61 38.1 270 top
C401  0.01uF  [0402]  160.53 38.1 270 top
C402  1000pF  [1206]  155.83 20.57 90 bottom
C403  0.1uF  [0402]  166.24 40.01 0 top
C404  0.1uF  [0402]  166.24 41.02 0 top
C405  1000pF  [1206]  155.83 28.96 270 bottom
C406  470pF  [0402]  152.27 50.16 270 top
C407  470pF  [0402]  151.26 52.2 270 top
C408  1000pF  [1206]  166.5 28.96 270 bottom
C409  4.7pF  [0402]  155.19 47.12 180 top
C410  4.7pF  [0402]  155.19 46.1 180 top
C411  1000pF  [0402]  154.05 42.67 180 bottom
C412  22uF  [0805]  154.81 41.15 180 bottom
C413  0.1uF  [0402]  153.16 41.53 90 top
C414  0.1uF  [0402]  165.74 52.7 270 bottom
C415  0.1uF  [0402]  158.88 53.09 0 bottom
C416  0.1uF  [0402]  157.1 46.48 0 bottom
C417  0.1uF  [0402]  160.4 44.96 90 bottom
C418  0.1uF  [0402]  167.64 44.96 90 bottom
C419  0.1uF  [0402]  166.12 44.96 90 bottom
C420  0.1uF  [0402]  164.21 44.96 90 bottom
C421  0.1uF  [0402]  162.69 44.96 90 bottom
C422  0.1uF  [0402]  161.42 44.96 90 bottom
C423  0.1uF  [0402]  159.39 44.96 90 bottom
C424  0.1uF  [0402]  158.88 47.88 0 bottom
C425  22uF  [0805]  154.56 44.45 180 top
C426  0.1uF  [0402]  157.35 52.96 90 bottom
C427  0.1uF  [0402]  164.34 52.7 270 bottom
C428  0.1uF  [0402]  157.86 45.09 0 bottom
C429  0.1uF  [0402]  167.01 50.67 180 bottom
C430  0.1uF  [0402]  167.01 48.26 180 bottom
C431  0.1uF  [0402]  186.18 92.58 270 top
C432  10uF  [0603]  178.18 90.04 270 top
C433  1uF  [0402]  186.56 89.41 180 bottom
C434  0.1uF  [0402]  187.2 92.58 270 top
C435  0.1uF  [0402]  188.09 82.55 90 bottom
C436  0.1uF  [0402]  192.02 81.91 90 bottom
C437  0.1uF  [0402]  187.07 87.88 270 bottom
C438  0.1uF  [0402]  190.12 82.55 90 bottom
C439  0.1uF  [0402]  183.01 81.15 180 bottom
C440  0.1uF  [0402]  188.85 89.66 180 bottom
C441  0.1uF  [0402]  186.06 82.55 90 bottom
C442  0.1uF  [0402]  191.64 92.58 270 top
C443  0.1uF  [0402]  190.63 92.58 270 top
C444  10uF  [0603]  176.91 81.53 180 top
C445  1uF  [0402]  183.52 82.68 90 bottom
C446  0.1uF  [0402]  189.1 82.55 90 bottom
C447  0.1uF  [0402]  187.07 82.55 90 bottom
C448  0.1uF  [0402]  184.53 82.68 90 bottom
C449  10uF  [0603]  178.82 87.88 180 top
C450  10uF  [0603]  178.82 86.49 180 top
C451  1uF  [0402]  189.61 85.09 180 bottom
C452  0.1uF  [0402]  186.06 87.76 270 bottom
C453  0.1uF  [0402]  188.47 88.14 90 bottom
C454  0.1uF  [0402]  186.06 84.2 0 bottom
C455  0.1uF  [0402]  190.75 88.52 90 bottom
C456  10uF  [0603]  197.61 90.42 0 top
C457  10uF  [0603]  182.25 93.09 90 top
C458  1uF  [0402]  189.61 86.11 180 bottom
C459  0.1uF  [0402]  186.31 86.23 0 bottom
C460  0.1uF  [0402]  189.48 87.63 90 bottom
C461  0.1uF  [0402]  189.61 84.07 180 bottom
C462  0.1uF  [0402]  186.31 85.22 0 bottom
C463  1uF  [0402]  187.33 74.68 270 top
C464  0.1uF  [0402]  217.93 92.58 270 top
C465  10uF  [0603]  209.93 90.04 270 top
C466  1uF  [0402]  218.31 89.41 180 bottom
C467  0.1uF  [0402]  214.76 81.15 180 bottom
C468  0.1uF  [0402]  220.6 89.66 180 bottom
C469  0.1uF  [0402]  218.82 87.88 270 bottom
C470  0.1uF  [0402]  218.95 92.58 270 top
C471  0.1uF  [0402]  217.81 82.55 90 bottom
C472  0.1uF  [0402]  221.87 82.55 90 bottom
C473  0.1uF  [0402]  219.84 82.55 90 bottom
C474  0.1uF  [0402]  223.77 81.91 90 bottom
C475  0.1uF  [0402]  223.39 92.58 270 top
C476  0.1uF  [0402]  222.38 92.58 270 top
C477  10uF  [0603]  208.66 81.53 180 top
C478  1uF  [0402]  215.27 82.68 90 bottom
C479  0.1uF  [0402]  216.28 82.68 90 bottom
C480  0.1uF  [0402]  220.85 82.55 90 bottom
C481  0.1uF  [0402]  218.82 82.55 90 bottom
C482  10uF  [0603]  210.57 87.88 180 top
C483  10uF  [0603]  210.57 86.49 180 top
C484  1uF  [0402]  221.36 85.09 180 bottom
C485  0.1uF  [0402]  217.81 87.76 270 bottom
C486  0.1uF  [0402]  217.81 84.2 0 bottom
C487  0.1uF  [0402]  222.5 88.52 90 bottom
C488  0.1uF  [0402]  220.22 88.14 90 bottom
C489  10uF  [0603]  229.36 90.42 0 top
C490  10uF  [0603]  214 93.09 90 top
C491  1uF  [0402]  221.36 86.11 180 bottom
C492  0.1uF  [0402]  218.06 86.23 0 bottom
C493  0.1uF  [0402]  218.06 85.22 0 bottom
C494  0.1uF  [0402]  221.23 87.63 90 bottom
C495  0.1uF  [0402]  221.36 84.07 180 bottom
C496  1uF  [0402]  219.08 74.68 270 top
C497  0.1uF  [0402]  217.3 42.8 90 bottom
C498  0.1uF  [0402]  185.55 42.8 90 bottom
C499  0.1uF  [0402]  214.38 42.8 90 bottom
C500  0.1uF  [0402]  182.63 42.8 90 bottom
C501  0.1uF  [0402]  211.33 42.8 90 bottom
C502  0.1uF  [0402]  179.58 42.8 90 bottom
C503  0.1uF  [0402]  208.41 42.8 90 bottom
C504  0.1uF  [0402]  176.66 42.8 90 bottom
C505  1000pF  [1206]  205.99 31.37 90 bottom
C506  1000pF  [1206]  174.24 31.37 90 bottom
C507  470pF  [0402]  231.65 82.17 180 top
C508  470pF  [0402]  199.9 82.17 180 top
C509  470pF  [0402]  231.65 81.15 180 top
C510  470pF  [0402]  199.9 81.15 180 top
C511  0.1uF  [0402]  217.3 65.66 90 bottom
C512  0.1uF  [0402]  185.55 65.66 90 bottom
C513  0.1uF  [0402]  214.38 65.66 90 bottom
C514  0.1uF  [0402]  182.63 65.66 90 bottom
C515  0.1uF  [0402]  211.33 65.66 90 bottom
C516  0.1uF  [0402]  179.58 65.66 90 bottom
C517  0.1uF  [0402]  208.41 65.66 90 bottom
C518  0.1uF  [0402]  176.66 65.66 90 bottom
C519  1000pF  [1206]  205.99 52.96 90 bottom
C520  1000pF  [1206]  174.24 52.96 90 bottom
C521  470pF  [0402]  231.65 80.14 180 top
C522  470pF  [0402]  199.9 80.14 180 top
C523  470pF  [0402]  225.81 82.93 90 bottom
C524  470pF  [0402]  194.06 82.93 90 bottom
C525  0.1uF  [0402]  233.17 42.8 90 bottom
C526  0.1uF  [0402]  201.42 42.8 90 bottom
C527  0.1uF  [0402]  230.25 42.8 90 bottom
C528  0.1uF  [0402]  198.5 42.8 90 bottom
C529  0.1uF  [0402]  227.2 42.8 90 bottom
C530  0.1uF  [0402]  195.45 42.8 90 bottom
C531  0.1uF  [0402]  224.28 42.8 90 bottom
C532  0.1uF  [0402]  192.53 42.8 90 bottom
C533  1000pF  [1206]  221.87 31.37 90 bottom
C534  1000pF  [1206]  190.12 31.37 90 bottom
C535  470pF  [0402]  227.2 84.96 270 bottom
C536  470pF  [0402]  195.45 84.96 270 bottom
C537  470pF  [0402]  231.65 85.22 180 top
C538  470pF  [0402]  199.9 85.22 180 top
C539  0.1uF  [0402]  233.17 65.66 90 bottom
C540  0.1uF  [0402]  230.25 65.66 90 bottom
C541  0.1uF  [0402]  201.42 65.66 90 bottom
C542  0.1uF  [0402]  198.5 65.66 90 bottom
C543  0.1uF  [0402]  227.2 65.66 90 bottom
C544  0.1uF  [0402]  195.45 65.66 90 bottom
C545  0.1uF  [0402]  224.28 65.66 90 bottom
C546  0.1uF  [0402]  192.53 65.66 90 bottom
C547  470pF  [0402]  199.9 84.2 180 top
C548  1000pF  [1206]  221.87 52.96 90 bottom
C549  1000pF  [1206]  190.12 52.96 90 bottom
C550  470pF  [0402]  199.9 83.19 180 top
C551  1000pF  [1206]  205.99 38.35 270 bottom
C552  1000pF  [1206]  174.24 38.35 270 bottom
C553  470pF  [0402]  231.65 84.2 180 top
C554  470pF  [0402]  231.65 83.19 180 top
C555  1000pF  [1206]  221.87 38.35 270 bottom
C556  0.1uF  [0402]  241.05 60.07 270 top
C557  4.7uF  [0603]  239.01 59.31 0 top
C558  0.01uF  [0402]  239.01 58.04 0 top
C559  1000pF  [1206]  232.79 37.59 270 bottom
C560  1000pF  [1206]  189.99 38.35 270 bottom
C737  0.1uF  [0402]  210.44 176.78 270 top
C738  0.1uF  [0402]  209.42 176.78 270 top
C739  0.1uF  [0402]  213.61 176.78 270 top
C740  0.1uF  [0402]  212.6 176.78 270 top
C741  0.1uF  [0402]  272.16 99.69 180 top
C742  10uF  [0603]  82.8 191.39 90 top
C743  10uF  [0603]  209.8 191.52 90 top
C744  0.1uF  [0402]  221.11 190.75 90 top
C745  0.1uF  [0402]  197.87 190.75 90 top
C746  0.1uF  [0402]  70.87 190.75 90 top
C747  0.1uF  [0402]  93.98 190.88 90 top
C748  0.1uF  [0402]  272.16 100.71 180 top
C749  0.1uF  [0402]  272.16 97.54 180 top
C750  0.1uF  [0402]  272.16 98.55 180 top
C751  10uF  [0603]  211.2 191.52 90 top
C752  10uF  [0603]  84.2 191.39 90 top
C753  0.1uF  [0402]  199.39 190.75 90 top
C754  0.1uF  [0402]  219.46 190.75 90 top
C755  0.1uF  [0402]  72.52 190.75 90 top
C756  0.1uF  [0402]  92.46 190.88 90 top
C757  0.1uF  [0402]  83.44 176.78 270 top
C758  100uF  [CAPE_B6D3]  268.61 80.77 180 top
C759  10uF  [1206]  268.86 75.82 180 top
C760  10uF  [1206]  280.42 77.47 0 top
C761  0.1uF  [0603]  277.11 77.22 270 top
C762  0.1uF  [0603]  275.59 77.22 270 top
C763  0.1uF  [0603]  274.07 77.22 270 top
C764  10uF  [0603]  271.65 93.09 180 top
C765  0.1uF  [0402]  272.16 91.82 180 top
C766  0.1uF  [0402]  272.16 90.81 180 top
C767  0.1uF  [0402]  272.16 89.79 180 top
C768  0.1uF  [0402]  82.42 176.78 270 top
C769  0.1uF  [0402]  86.61 176.78 270 top
C770  0.1uF  [0402]  85.6 176.78 270 top
C771  0.01uF  [0402]  190.25 132.08 0 top
C772  0.01uF  [0402]  190.25 131.06 0 top
C773  0.01uF  [0402]  190.25 128.27 0 top
C774  0.01uF  [0402]  190.25 127.25 0 top
C775  0.01uF  [0402]  227.08 123.57 270 top
C776  0.01uF  [0402]  226.06 123.57 270 top
C777  1uF  [0402O]  45.97 97.89 270 bottom
C778  0.1uF  [0402O]  44.47 96.39 180 bottom
C779  0.1uF  [0402O]  46.47 95.38 0 bottom
C780  0.1uF  [0402O]  47.47 94.38 180 bottom
C781  1uF  [0402O]  44.97 93.88 90 bottom
C782  0.1uF  [0402O]  43.46 97.39 0 bottom
C783  0.1uF  [0402O]  43.46 94.38 0 bottom
C784  0.1uF  [0402O]  38.46 88.38 180 bottom
C785  0.1uF  [0402O]  38.46 89.38 0 bottom
C786  0.1uF  [0402O]  52.47 88.38 0 bottom
C787  0.1uF  [0402O]  38.46 102.39 0 bottom
C788  0.1uF  [0402O]  45.97 93.88 90 bottom
C789  1uF  [0402O]  46.47 96.39 180 bottom
C790  0.1uF  [0402O]  44.47 95.38 0 bottom
C791  0.1uF  [0402O]  52.47 89.38 180 bottom
C792  0.1uF  [0402O]  38.46 103.39 180 bottom
C793  0.1uF  [0402O]  52.47 102.39 180 bottom
C794  0.1uF  [0402O]  52.47 103.39 0 bottom
C795  0.1uF  [0402O]  47.47 97.39 180 bottom
C796  0.1uF  [0402O]  44.97 97.89 270 bottom
C797  10pF  [0402]  39.37 128.27 0 top
C798  0.1uF  [0402]  27.69 127.51 270 top
C799  0.01uF  [0402]  26.67 127.51 270 top
C800  1uF  [0402]  28.7 127.51 270 top
C801  0.1uF  [0402]  29.72 127.51 270 top
C802  10pF  [0402]  39.37 136.4 0 top
C803  0.1uF  [0402]  27.69 135.64 270 top
C804  0.01uF  [0402]  26.67 135.64 270 top
C805  1uF  [0402]  28.7 135.64 270 top
C806  0.1uF  [0402]  29.72 135.64 270 top
C807  10pF  [0402]  39.37 120.14 0 top
C808  0.1uF  [0402]  27.69 119.38 270 top
C809  0.01uF  [0402]  26.67 119.38 270 top
C810  1uF  [0402]  28.7 119.38 270 top
C811  0.1uF  [0402]  29.72 119.38 270 top
C812  0.1uF  [0402]  27.56 101.6 0 top
C813  0.01uF  [0402]  27.56 100.58 0 top
C814  1uF  [0402]  22.48 100.84 180 top
C815  0.1uF  [0402]  22.48 99.82 180 top
C816  4.7pF  [0402]  201.8 91.31 90 top
C817  4.7pF  [0402]  207.39 90.93 270 top
C818  0.1uF  [0402]  197.49 93.34 180 top
C819  0.1uF  [0402]  208.28 97.03 0 top
C820  0.1uF  [0402]  201.93 102.49 180 top
C821  0.1uF  [0402]  208.28 100.33 0 top
C822  10uF  [0603]  197.1 96.65 180 top
C823  0.01uF  [0402]  197.49 95.38 180 top
C824  2pF  [0402]  237.36 126.24 180 top
C825  2pF  [0402]  239.4 126.24 0 top
C826  10uF  [0603]  238 125.86 180 bottom
C827  0.01uF  [0402]  238 127.63 90 bottom
C828  0.1uF  [0402]  236.6 131.44 0 bottom
C829  0.1uF  [0402]  240.28 127.51 90 bottom
C830  0.1uF  [0402]  236.86 129.16 0 bottom
C831  0.1uF  [0402]  238.51 132.59 270 bottom
C832  0.1uF  [0402]  241.68 131.57 180 bottom
C833  0.1uF  [0402]  241.55 129.03 180 bottom
C834  10uF  [0603]  240.41 134.87 0 bottom
C835  0.01uF  [0402]  239.52 132.59 270 bottom
C836  10uF  [0603]  236.47 123.7 270 bottom
C837  0.1uF  [0402]  241.68 130.56 180 bottom
C838  0.1uF  [0402]  236.22 133.48 90 bottom
C839  0.1uF  [0402]  241.81 127.51 180 bottom
C840  0.33uF  [0603]  69.34 101.47 90 top
C841  22uF  [1206]  73.15 97.03 270 bottom
C842  22uF  [1206]  70.74 102.87 90 bottom
C843  22uF  [1206]  70.74 97.03 270 bottom
C844  1uF  [0603]  70.23 93.34 0 top
C845  1uF  [0603]  71.63 101.35 0 top
C846  1uF  [0402]  66.04 100.97 270 top
C847  0.1uF  [0402]  63.88 95.89 270 top
C848  470uF  [7343]  92.58 94.23 0 top
C849  470uF  [7343]  92.58 99.57 0 top
C850  47uF  [0805]  92.71 88.39 0 top
C851  47uF  [0805]  92.71 90.55 0 top
C852  510pF  [0402]  65.41 96.39 0 top
C853  0.1uF  [0402]  79.38 87.25 270 top
C854  1uF  [0402]  68.83 95 90 bottom
C855  0.1uF  [0402]  67.82 96.01 90 bottom
C856  0.1uF  [0402]  63.37 92.2 270 top
C857  0.1uF  [0402]  94.62 107.44 0 top
C858  0.1uF  [0402]  76.84 87.38 0 bottom
C859  1uF  [0603]  186.17 141.1 0 top
C862  1uF  [0603]  187.57 149.1 0 top
C864  22uF  [1206]  187.19 145.41 90 bottom
C865  4.7uF  [0603]  192.02 140.97 90 top
C867  0.47uF  [0603]  188.46 140.97 270 top
C870  22uF  [1206]  184.79 145.41 90 bottom
C871  0.1uF  [0402]  178.44 141.1 0 bottom
C875  47uF  [0805]  178.31 142.62 0 bottom
C876  47uF  [0805]  178.31 148.34 0 bottom
C878  0.1uF  [0402]  193.93 146.56 270 top
C880  560pF  [0402]  192.4 146.05 0 top
C885  1uF  [0402]  188.97 147.45 270 bottom
C886  0.1uF  [0402]  189.98 146.56 270 bottom
C887  47uF  [0805]  178.31 146.43 0 bottom
C888  47uF  [0805]  178.31 144.53 0 bottom
C889  22uF  [1206]  38.99 60.96 270 bottom
C890  0.47uF  [0603]  35.31 65.41 90 top
C891  1uF  [0603]  27.43 163.58 270 top
C892  1uF  [0603]  36.2 57.28 180 top
C893  1uF  [0603]  35.43 162.19 270 top
C894  22uF  [1206]  31.75 162.57 0 bottom
C895  22uF  [1206]  31.75 164.97 0 bottom
C896  0.47uF  [0603]  27.31 161.3 180 top
C897  1uF  [0603]  37.6 65.28 180 top
C898  22uF  [1206]  36.58 60.96 270 bottom
C899  0.01uF  [0402]  27.81 158 0 top
C900  0.01uF  [0402]  32.01 64.9 270 top
C901  47uF  [0805]  45.47 58.04 180 bottom
C902  0.1uF  [0402]  32.89 155.83 180 top
C903  47uF  [0805]  28.96 171.45 270 bottom
C904  47uF  [0805]  30.86 171.45 270 bottom
C905  0.1uF  [0402]  27.43 171.32 270 bottom
C906  47uF  [0805]  45.47 61.85 180 bottom
C907  0.1uF  [0402]  45.34 65.28 180 bottom
C908  0.1uF  [0402]  29.85 59.82 90 top
C909  560pF  [0402]  32.39 157.36 270 top
C910  620pF  [0402]  31.38 60.33 180 top
C911  1uF  [0402]  33.78 160.79 180 bottom
C912  0.01uF  [0402]  32.89 159.77 180 bottom
C913  47uF  [0805]  34.67 171.45 270 bottom
C914  47uF  [0805]  32.77 171.45 270 bottom
C915  1uF  [0402]  34.81 58.93 90 bottom
C916  0.01uF  [0402]  33.79 59.82 90 bottom
C917  47uF  [0805]  45.47 63.75 180 bottom
C918  47uF  [0805]  45.47 59.94 180 bottom
C919  1uF  [0603]  249.17 75.18 0 top
C920  1uF  [0603]  249.05 72.89 90 top
C921  1uF  [0603]  34.67 46.1 180 top
C922  22uF  [1206]  244.73 73.91 180 bottom
C923  22uF  [1206]  244.73 71.5 180 bottom
C924  22uF  [1206]  37.47 49.78 270 bottom
C925  1uF  [0603]  241.05 74.29 90 top
C926  1uF  [0603]  36.07 54.1 180 top
C927  22uF  [1206]  31.75 53.59 180 bottom
C928  0.01uF  [0402]  248.67 78.48 180 top
C929  0.01uF  [0402]  30.48 53.72 270 top
C930  1uF  [0603]  33.78 54.23 90 top
C931  47uF  [0805]  247.52 65.02 90 bottom
C932  47uF  [0805]  241.81 65.02 90 bottom
C933  47uF  [0805]  43.94 48.9 180 bottom
C934  0.1uF  [0402]  249.05 65.15 90 bottom
C935  47uF  [0805]  43.94 50.8 180 bottom
C936  0.1uF  [0402]  43.18 54.48 180 top
C937  0.1uF  [0402]  243.59 80.64 0 top
C938  0.1uF  [0402]  28.32 48.64 90 top
C939  680pF  [0402]  244.09 79.11 90 top
C940  680pF  [0402]  29.85 49.15 180 top
C941  1uF  [0402]  242.7 75.68 0 bottom
C942  0.01uF  [0402]  243.59 76.7 0 bottom
C943  47uF  [0805]  245.62 65.02 90 bottom
C944  47uF  [0805]  243.71 65.02 90 bottom
C945  1uF  [0402]  33.27 47.75 90 bottom
C946  0.01uF  [0402]  32.26 48.64 90 bottom
C947  47uF  [0805]  43.94 54.61 180 bottom
C948  22uF  [1206]  35.05 49.78 270 bottom
C949  22uF  [1206]  38.99 53.59 0 bottom
C950  47uF  [0805]  43.94 52.7 180 bottom
C951  47uF  [0805]  43.94 46.99 180 bottom
C952  1uF  [0603]  247.13 93.34 0 top
C953  0.33uF  [0603]  248.02 85.22 270 top
C954  1uF  [0603]  245.74 85.34 0 top
C957  0.01uF  [0402]  251.33 85.72 90 top
C960  22uF  [1206]  244.35 89.66 90 bottom
C961  22uF  [1206]  246.75 89.66 90 bottom
C964  47uF  [0805]  237.87 86.87 0 bottom
C966  0.1uF  [0402]  253.49 90.81 270 top
C967  47uF  [0805]  237.87 92.58 0 bottom
C968  0.1uF  [0402]  238 85.34 0 bottom
C972  510pF  [0402]  251.96 90.3 0 top
C974  1uF  [0402]  248.53 91.69 270 bottom
C975  0.01uF  [0402]  249.55 90.81 270 bottom
C976  47uF  [0805]  237.87 88.77 0 bottom
C977  47uF  [0805]  237.87 90.68 0 bottom
C991  10uF  [0603]  127.64 171.83 0 top
C992  10uF  [0603]  128.65 170.43 0 top
C995  4.7uF  [0603]  122.56 169.93 0 top
C996  0.1uF  [0402]  120.14 174.24 180 top
C997  1uF  [0402]  130.68 170.69 90 top
C998  22uF  [0805]  127.13 174.24 90 top
C999  22uF  [0805]  129.03 174.24 90 top
C1004  1000pF  [0402]  125.1 169.16 180 top
C1005  10uF  [0603]  189.36 151.38 0 top
C1006  0.1uF  [0402]  189.87 152.65 0 top
C1007  10uF  [0603]  189.87 154.94 0 top
C1008  0.1uF  [0402]  189.87 153.67 0 top
C1009  1uF  [0402]  173.74 118.87 270 top
C1010  1uF  [0402]  170.56 121.28 0 top
C1011  1500pF  [0402]  183.64 155.45 270 bottom
C1012  10uF  [0603]  173.86 116.33 90 top
C1013  0.1uF  [0402]  175.13 116.2 90 top
C1014  NFM21PC225B0J3  [NFM21]  189.48 157.48 90 top
C1015  1uF  [0402]  173.1 124.33 90 top
C1016  1uF  [0402]  170.69 126.87 180 top
C1017  10uF  [0603]  168.02 121.54 0 top
C1018  0.1uF  [0402]  167.89 120.27 0 top
C1019  47uF  [0805]  190.25 160.27 0 top
C1020  0.1uF  [0402]  185.8 169.67 90 top
C1021  0.1uF  [0402]  187.83 169.67 90 top
C1022  0.1uF  [0402]  186.94 160.27 270 top
